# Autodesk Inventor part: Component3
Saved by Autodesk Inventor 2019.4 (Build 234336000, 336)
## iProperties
Created: 2020-02
Part Number: Component3
Material: Generic
Document SubType Name: Modeling
Designer: Administrator
Density: 1 g/cm^3
Appearance: Default
Title: Component3
Author: Administrator
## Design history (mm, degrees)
